Omron CX-Programmer project NewProject (CX-Programmer 6.11)

# PLC NewPLC1: CJ1M CPU12
I/O table (CPU CJ1M-CPU12): rack 0 slot 0 CJ1W-ID211; rack 0 slot 1 CJ1W-OC211

## Program NewProgram1 (cyclic task 0)
Local symbols
Clear 80.01 BOOL  ; Test Bit
Data_CLEAR 30.03 BOOL  ; Set in xycom screen under Data log
File_Full_bit 30.02 BOOL  ; .
Flip 75.00 BOOL  ; Test Bit
Flop 75.01 BOOL  ; Test Bit
GP_ACK_bit 30.01 BOOL  ; Set in xycom screen under Data log
Go 75.02 BOOL  ; Test Bit
IN_Cycle 50.00 BOOL  ; Test We are in cycle
Log 80.02 BOOL  ; Test Bit
PLC_trigger_bit 30.00 BOOL  ; Set in xycom screen under Data log
WRITE_CSV 40.00 BOOL  ; Test Bit

### Section Data

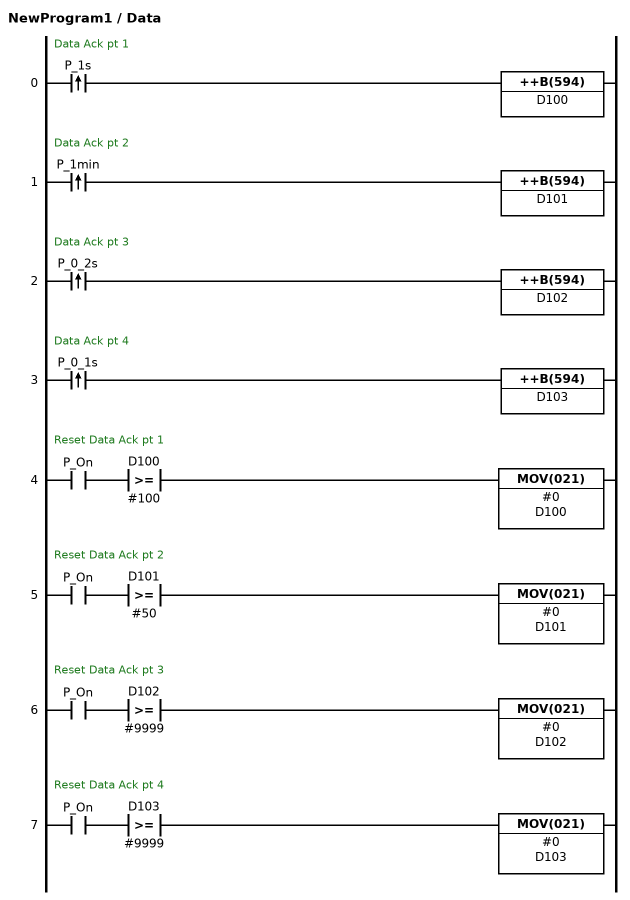
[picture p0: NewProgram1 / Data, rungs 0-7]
; rung 0: Data Ack pt 1
@LD P_1s
++B(594) D100
; rung 1: Data Ack pt 2
@LD P_1min
++B(594) D101
; rung 2: Data Ack pt 3
@LD P_0_2s
++B(594) D102
; rung 3: Data Ack pt 4
@LD P_0_1s
++B(594) D103
; rung 4: Reset Data Ack pt 1
LD P_On
AND>=(325) D100 #100
MOV(021) #0 D100
; rung 5: Reset Data Ack pt 2
LD P_On
AND>=(325) D101 #50
MOV(021) #0 D101
; rung 6: Reset Data Ack pt 3
LD P_On
AND>=(325) D102 #9999
MOV(021) #0 D102
; rung 7: Reset Data Ack pt 4
LD P_On
AND>=(325) D103 #9999
MOV(021) #0 D103

### Section LOG

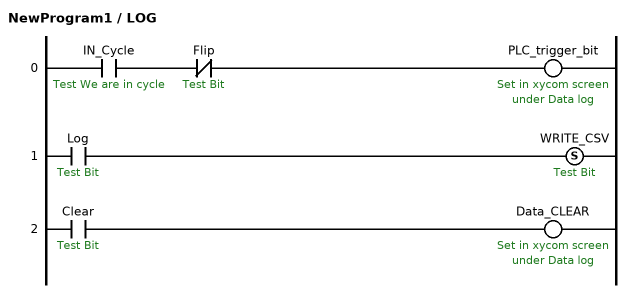
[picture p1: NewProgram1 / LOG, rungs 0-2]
; rung 0
LD IN_Cycle  ; Test We are in cycle
ANDNOT Flip  ; Test Bit
OUT PLC_trigger_bit  ; Set in xycom screen under Data log
; rung 1
LD Log  ; Test Bit
SET WRITE_CSV  ; Test Bit
; rung 2
LD Clear  ; Test Bit
OUT Data_CLEAR  ; Set in xycom screen under Data log

### Section flipflop

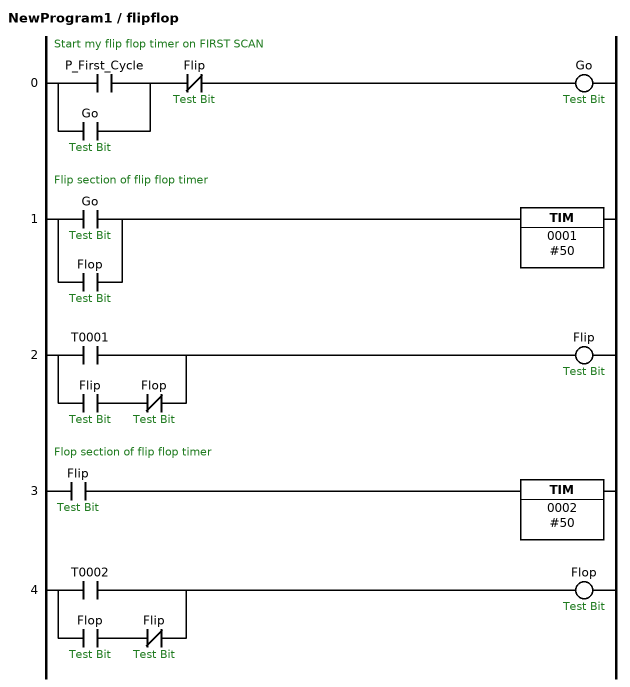
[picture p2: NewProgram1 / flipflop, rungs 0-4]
; rung 0: Start my flip flop timer on FIRST SCAN
LD P_First_Cycle
OR Go  ; Test Bit
ANDNOT Flip  ; Test Bit
OUT Go  ; Test Bit
; rung 1: Flip section of flip flop timer
LD Go  ; Test Bit
OR Flop  ; Test Bit
TIM 0001 #50
; rung 2
LD T0001
LD Flip  ; Test Bit
ANDNOT Flop  ; Test Bit
ORLD
OUT Flip  ; Test Bit
; rung 3: Flop section of flip flop timer
LD Flip  ; Test Bit
TIM 0002 #50
; rung 4
LD T0002
LD Flop  ; Test Bit
ANDNOT Flip  ; Test Bit
ORLD
OUT Flop  ; Test Bit

### Section END
; rung 0
END(001)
